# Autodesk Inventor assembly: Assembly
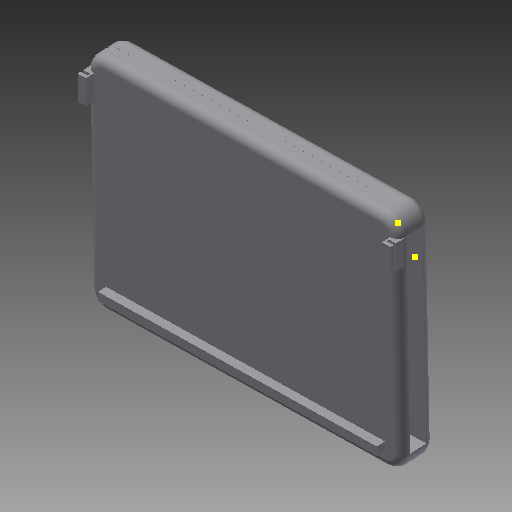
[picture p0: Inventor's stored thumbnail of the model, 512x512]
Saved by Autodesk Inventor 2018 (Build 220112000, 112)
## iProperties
Created: 2017-07
Part Number: Assembly
Document SubType Name: Assembly
Designer: 17046589
Author: 17046589
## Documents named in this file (7)
- C:\Users\17046589\Downloads\LAPTOP STAND\Assembly.iam
- C:\Users\17046589\Downloads\LAPTOP STAND\Second Board.ipt
- C:\Users\17046589\Downloads\LAPTOP STAND\Phone Holder.ipt
- C:\Users\17046589\Downloads\LAPTOP STAND\LED Light.ipt
- C:\Users\17046589\Downloads\LAPTOP STAND\Cup Holder.ipt
- C:\Users\17046589\Downloads\LAPTOP STAND\First Board.ipt
- C:\Users\17046589\Downloads\LAPTOP STAND\Hinge 2.ipt
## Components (7 placed, 6 different names)
1. Second Board:1 — Mate:2, Mate:3, Mate:4, Rigid:1
2. LED Light:1 — Mate:2
3. Phone Holder:1 — Mate:3
4. Cup Holder:1 — Mate:4
5. First Board:1 — Mate:5, Mate:6, Rigid:1, Mate:7
6. Hinge 2:1 — Mate:5
7. Hinge 2:2 — Mate:6, Mate:7
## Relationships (7: Mate 6, WeldJoint 1)
- Mate:2: Second Board:1 ↔ LED Light:1
- Mate:3: Second Board:1 ↔ Phone Holder:1
- Mate:4: Second Board:1 ↔ Cup Holder:1
- Mate:5: First Board:1 ↔ Hinge 2:1
- Mate:6: First Board:1 ↔ Hinge 2:2
- Rigid:1 [WeldJoint]: Second Board:1 ↔ First Board:1
- Mate:7: First Board:1 ↔ Hinge 2:2
